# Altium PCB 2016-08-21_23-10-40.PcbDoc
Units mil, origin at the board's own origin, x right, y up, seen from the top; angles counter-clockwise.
Board outline 3246 x 2920 mil, 4 copper layers (Top Layer, MidLayer1, MidLayer2, Bottom Layer); 48 components, 32 nets, 132 pads, 110 vias.
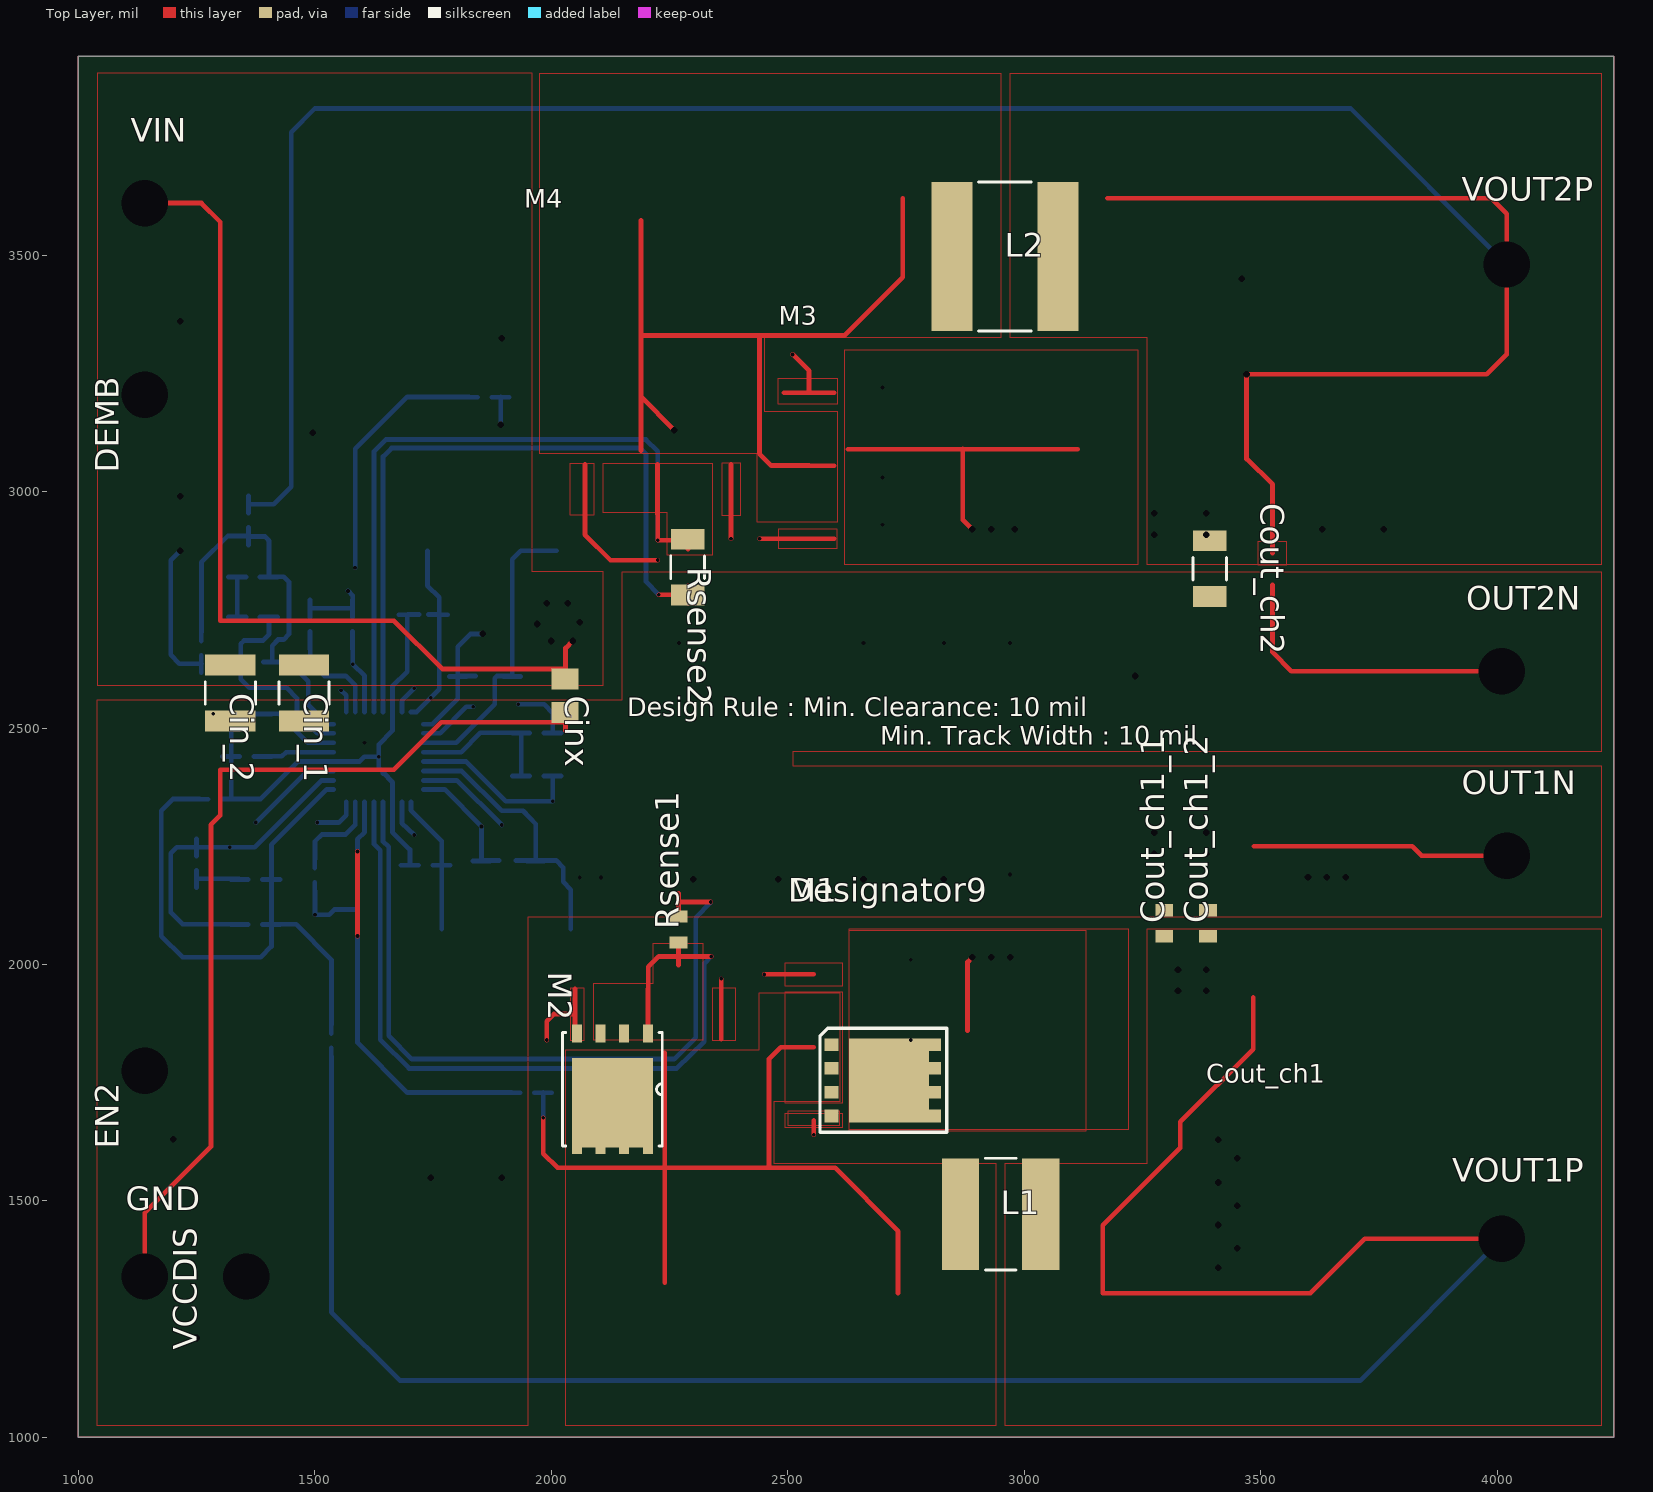
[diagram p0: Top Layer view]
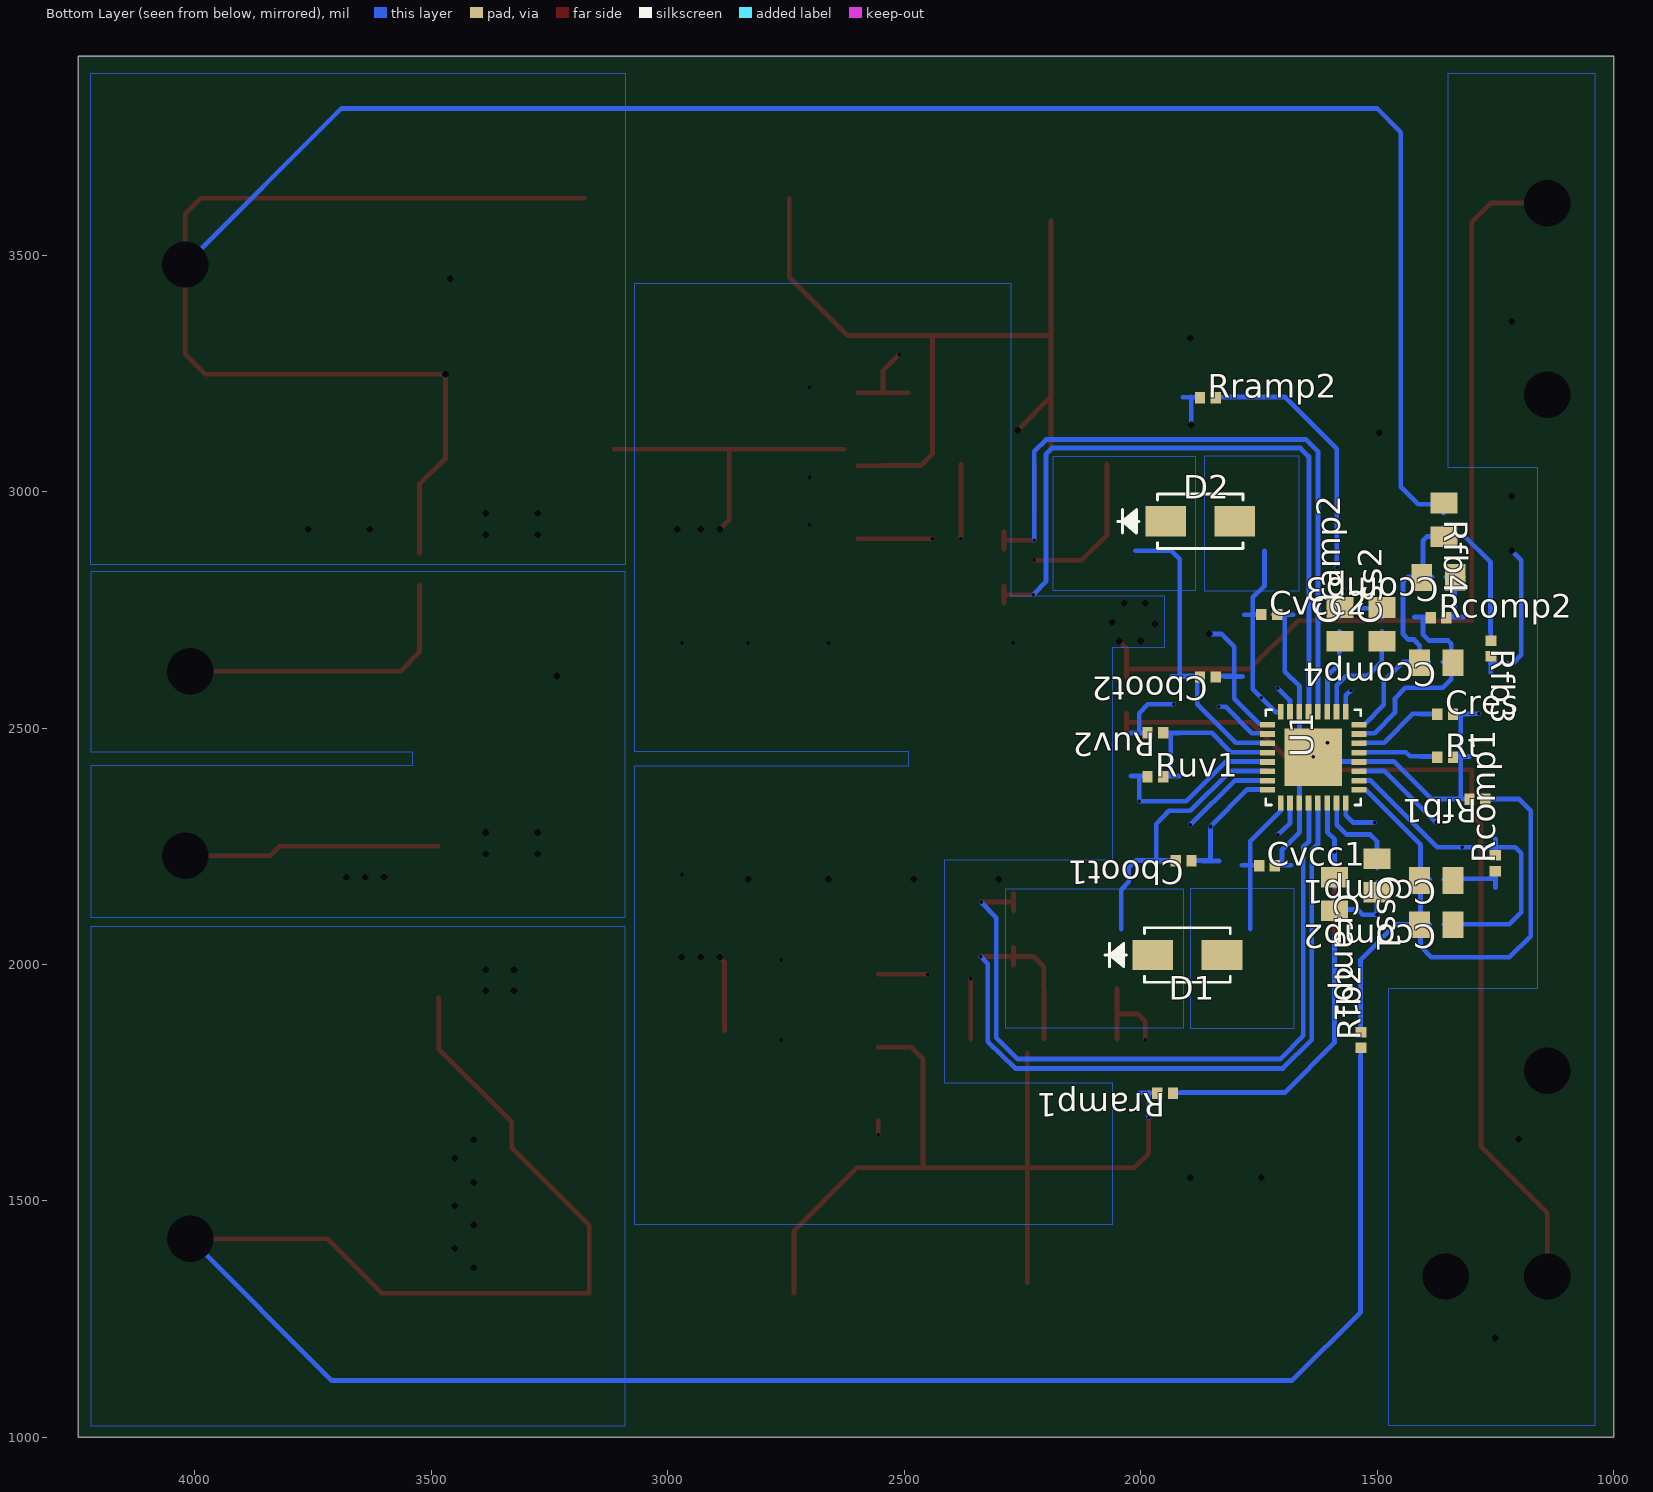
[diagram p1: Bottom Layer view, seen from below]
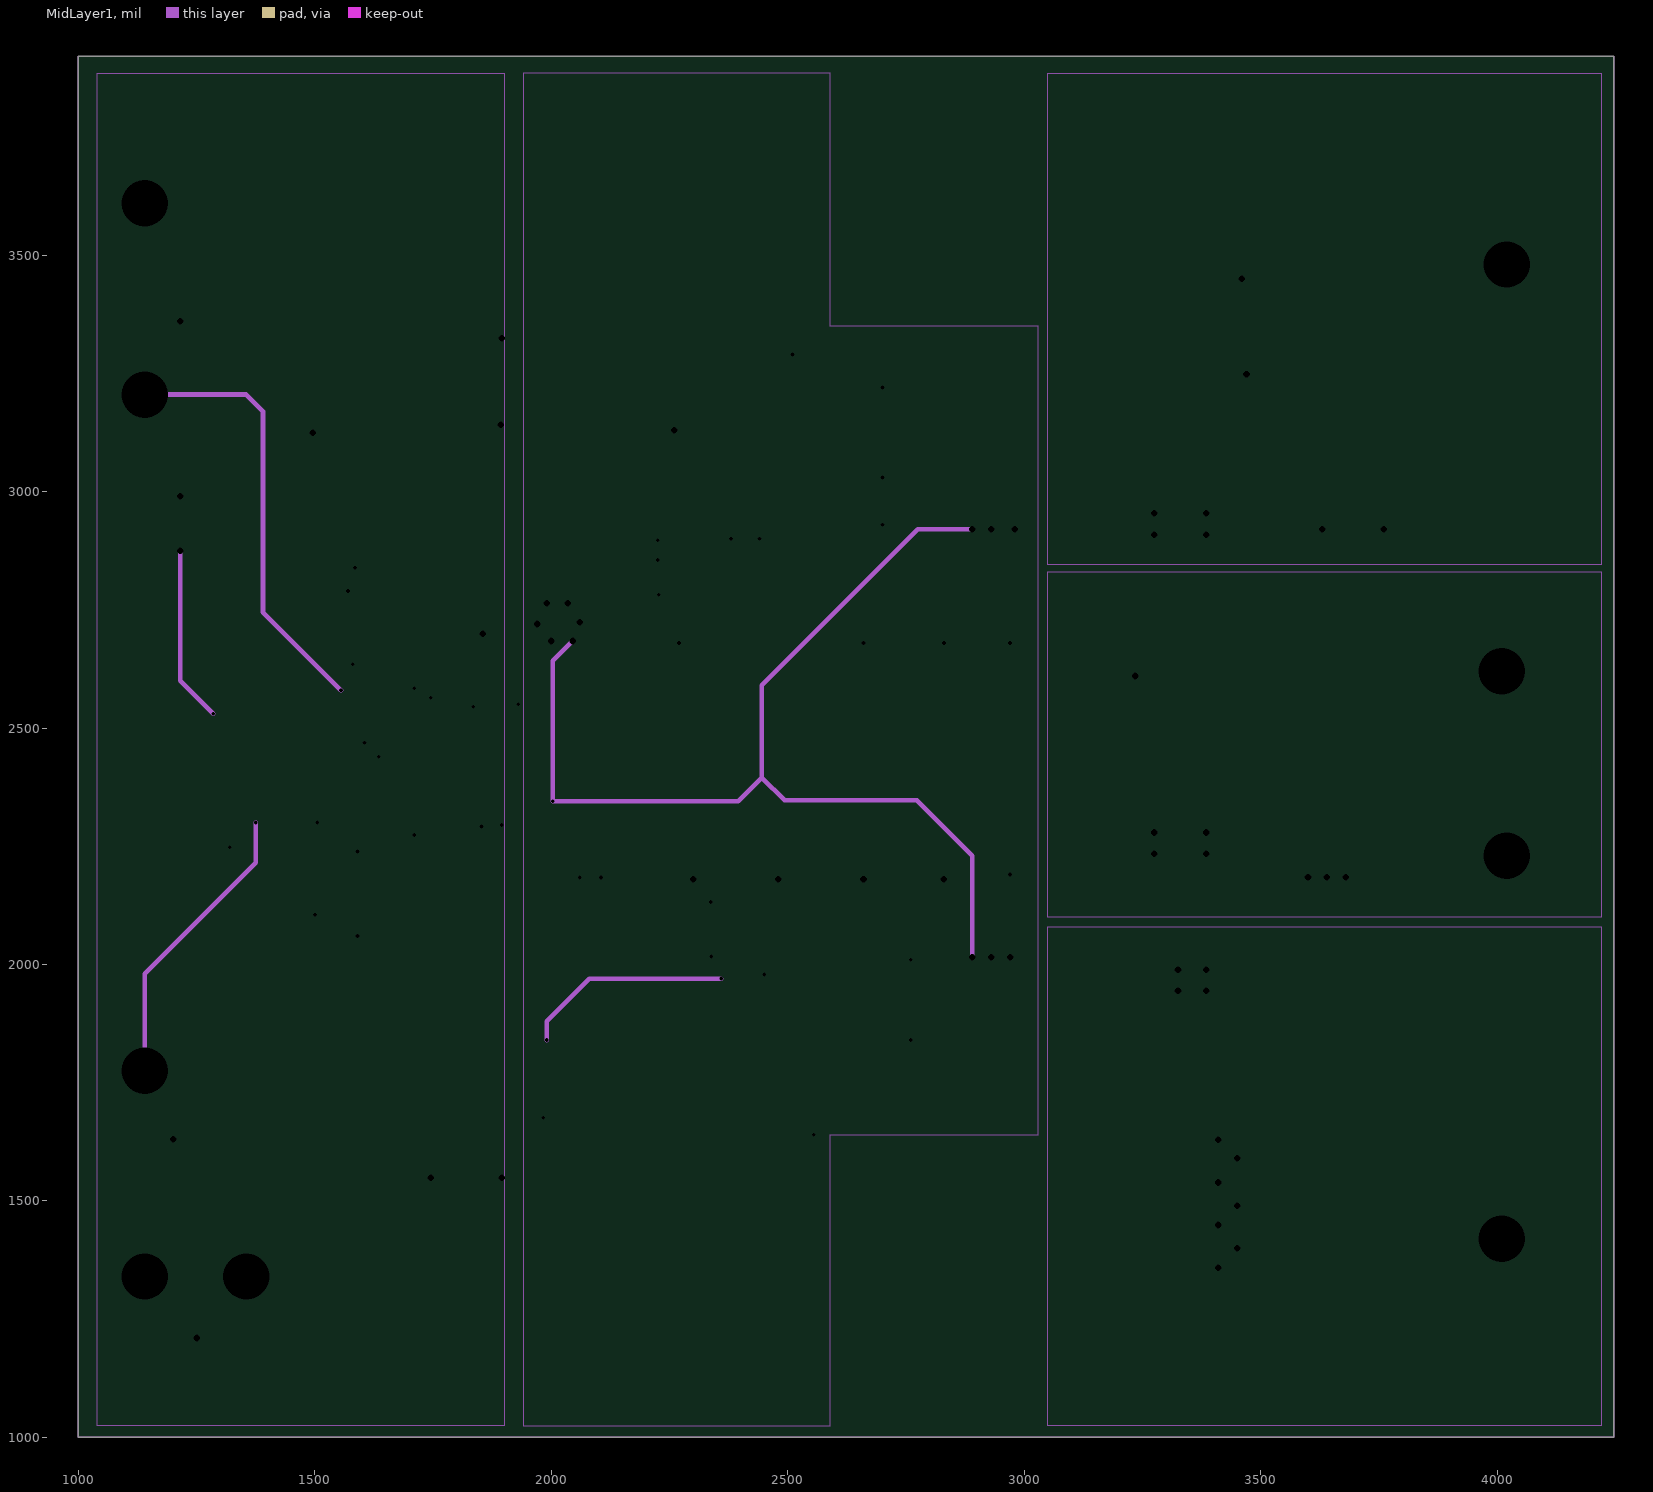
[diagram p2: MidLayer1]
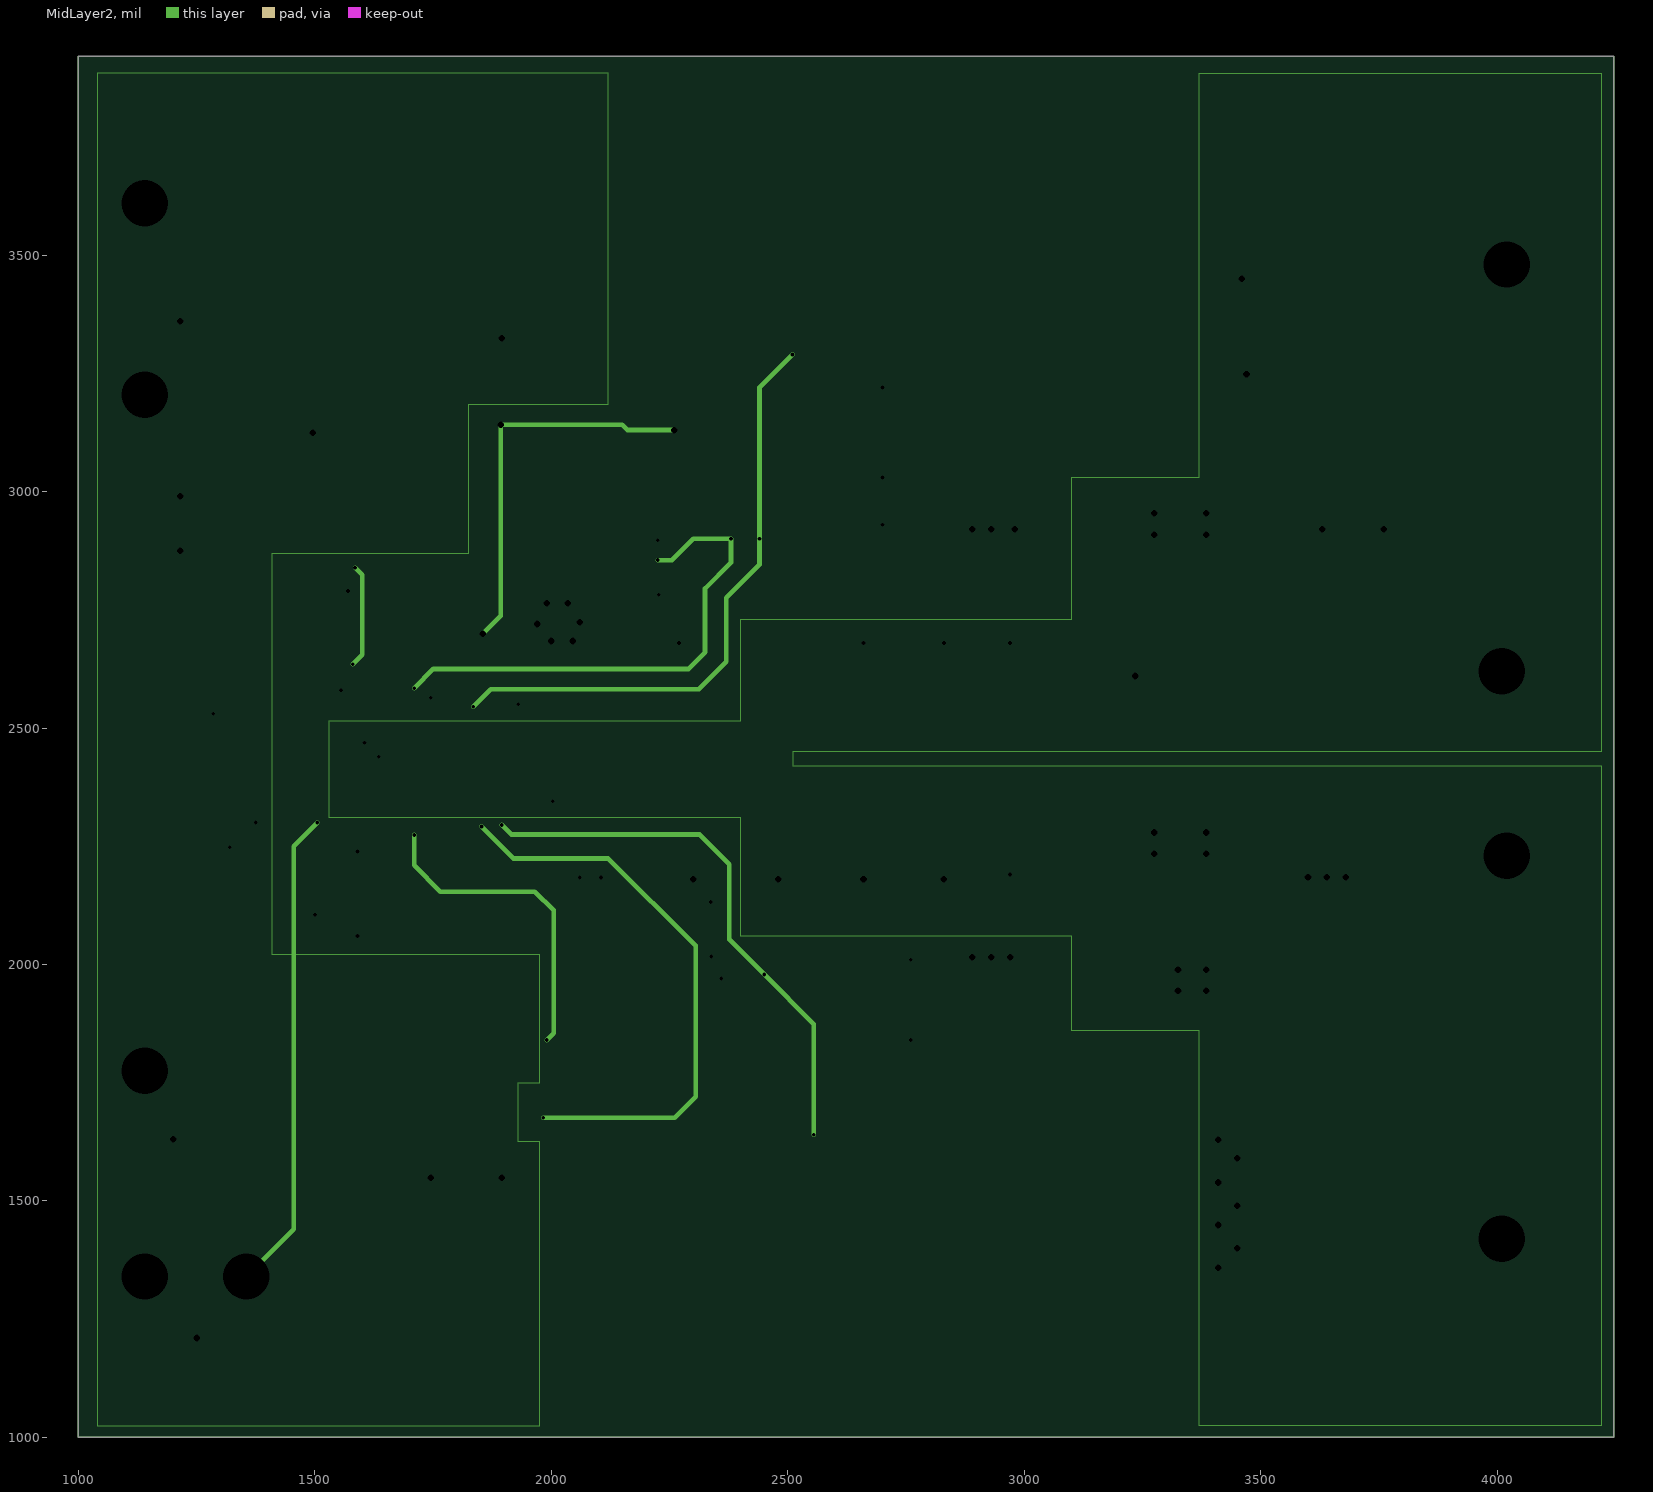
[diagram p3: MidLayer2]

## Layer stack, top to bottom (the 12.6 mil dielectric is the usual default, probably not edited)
Top Layer: signal copper 1.4
Dielectric: core 12.6, FR-4, Dk 4.8
MidLayer1: signal copper 1.4
Dielectric: prepreg 12.6, FR-4, Dk 4.8
MidLayer2: signal copper 1.4
Dielectric: core 12.6, FR-4, Dk 4.8
Bottom Layer: signal copper 1.4

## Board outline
1000,1000 4246,1000 4246,3920 1000,3920

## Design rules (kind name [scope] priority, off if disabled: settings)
PlaneConnect [All] p0: scope1count=1 scope1_0_kind=Board scope1_0_value=Board scope2count=1 scope2_0_kind=Board scope2_0_value=Board commentlength=0 planeconnectstyle=Direct reliefexpansion=20 reliefentries=4 reliefconductorwidth=10 reliefairgap=10
PlaneConnect [All] p1: planeconnectstyle=Direct reliefexpansion=20 reliefentries=4 reliefconductorwidth=10 reliefairgap=10
PolygonConnect [All] p0: scope1count=1 scope1_0_kind=Board scope1_0_value=Board scope2count=1 scope2_0_kind=Board scope2_0_value=Board commentlength=0 connectstyle=Direct reliefconductorwidth=10 reliefentries=4 polygonreliefangle="90 Angle"
PolygonConnect [All] p1: connectstyle=Direct reliefconductorwidth=10 reliefentries=4 polygonreliefangle="90 Angle"

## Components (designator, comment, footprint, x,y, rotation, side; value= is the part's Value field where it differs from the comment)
Cboot1 "" 0402 1909,2219 r180 bottom
Cboot2 "" 0402 1858,2608 r180 bottom
Ccomp1 "" 0805#1 1375,2178 r180 bottom
Ccomp2 "" 0805#1 1375,2084 r180 bottom
Ccomp3 "" 0805#1 1370,2818 r180 bottom
Ccomp4 "" 0805#1 1375,2638 r180 bottom
Cin_1 "" 1210_280 1477,2574 r270 top
Cin_2 "" 1210_280 1321,2574 r270 top
Cinx "" 0805#2 2029,2568 r270 top
Cout_ch1_1 "" 0603 3296,2087 r90 top
Cout_ch1_2 "" 0603 3388,2087 r90 top
Cout_ch2 "" 1206_190 3392,2837 r270 top
Cramp1 "" 0805#1 1590,2149 r90 bottom
Cramp2 "" 0805#1 1578,2719 r270 bottom
Cres "" 0402 1356,2529 r0 bottom
Css1 "" 0805#1 1500,2188 r90 bottom
Css2 "" 0805#1 1490,2719 r270 bottom
Cvcc1 "" 0402 1733,2209 r0 bottom
Cvcc2 "" 0402 1728,2740 r0 bottom
D1 "" SMA 1901,2020 r0 bottom
D2 "" SMA 1874,2937 r0 bottom
DEMB "" TP-1502 1138,3203 r90 top
EN2 "" TP-1502 1138,1774 r90 top
GND "" TP-1502 1138,1340 r0 top
L1 "" SRN6045 2950,1472 r0 top
L2 "" SRN8040 2959,3497 r0 top
M1 "" TRANS_NexFET_Q5A 2702,1755 r0 top
M2 "" PG-TDSON-8 2129,1736 r270 top
OUT1N "" TP-1502 4019,2228 r0 top
OUT2N "" TP-1502 4009,2620 r0 top
Rcomp1 "" 0402 1250,2214 r270 bottom
Rcomp2 "" 0402 1370,2733 r0 bottom
Rfb1 "" 0402 1288,2349 r180 bottom
Rfb2 "" 0402 1534,1840 r270 bottom
Rfb3 "" 0402 1259,2668 r90 bottom
Rfb4 "" 0805#1 1358,2940 r90 bottom
Rramp1 "" 0402 1948,1728 r180 bottom
Rramp2 "" 0402 1858,3198 r0 bottom
Rsense1 "" 0603 2269,2074 r90 top
Rsense2 "" 1206 2288,2840 r270 top
Rt "" 0402 1356,2438 r0 bottom
Ruv1 "" 0402 1969,2397 r0 bottom
Ruv2 "" 0402 1969,2490 r180 bottom
U1 "" SQA32A 1635,2438 r270 bottom
VCCDIS "" TP-1502 1353,1340 r90 top
VIN "" TP-1502 1138,3608 r0 top
VOUT1P "" TP-1502 4009,1418 r0 top
VOUT2P "" TP-1502 4019,3478 r0 top

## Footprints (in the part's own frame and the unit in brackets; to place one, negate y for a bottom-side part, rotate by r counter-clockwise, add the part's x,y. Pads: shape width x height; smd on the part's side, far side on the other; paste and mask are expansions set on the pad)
0402 [mil]
  rect 22x24 smd: 1(16.5,0) 2(-16.5,0)
0603 [mil]
  rect 26x38 smd: 1(-27.5,0) 2(27.5,0)
0805#1 [mil]
  rect 44x57 smd: 1(35.5,0) 2(-35.5,0)
0805#2 [mil]
  rect 44x57 smd: 1(-35.5,0) 2(35.5,0)
1206 [mil]
  rect 44x71 smd: 1(-59,0) 2(59,0)
  silkscreen extent -24,-36 24,36
1206_190 [mil]
  rect 44x71 smd: 1(-59,0) 2(59,0)
  silkscreen extent -24,-36 24,36
1210_280 [mil]
  rect 44x106 smd: 1(-59,0) 2(59,0)
  silkscreen extent -24,-53 24,53
PG-TDSON-8 [mil]
  rect 38x21 smd: 1(-118,75) 2(-118,25) 3(-118,-25) 4(-118,-75) 5(118,-75) 6(118,-25) 7(118,25) 8(118,75)
  rect 189.17x171.65 smd: 9(28.54,0)
  silkscreen extent -120,-106 120,106
SMA [mil]
  rect 86x64 smd: 1(73,0) 2(-73,0)
  silkscreen extent -90,-58 174,58
SQA32A [mil]
  rect 32x12 smd: 1(96.5,-68.9) 2(96.5,-49.21) 3(96.5,-29.53) 4(96.5,-9.84) 5(96.5,9.84) 6(96.5,29.53) 7(96.5,49.21) 8(96.5,68.9) 17(-96.5,68.9) 18(-96.5,49.21) 19(-96.5,29.53) 20(-96.5,9.84) 21(-96.5,-9.84) 22(-96.5,-29.53) 23(-96.5,-49.21) 24(-96.5,-68.9)
  rect 12x32 smd: 9(68.9,96.5) 10(49.21,96.5) 11(29.53,96.5) 12(9.84,96.5) 13(-9.84,96.5) 14(-29.53,96.5) 15(-49.21,96.5) 16(-68.9,96.5) 25(-68.9,-96.5) 26(-49.21,-96.5) 27(-29.53,-96.5) 28(-9.84,-96.5) 29(9.84,-96.5) 30(29.53,-96.5) 31(49.21,-96.5) 32(68.9,-96.5)
  rect 122x122 smd: 33(0,0)
  silkscreen extent -101,-101 101,101
SRN6045 [mm]
  rect 2x6 smd: 1(-2.15,0) 2(2.15,0)
  silkscreen extent -0.82,-3 0.82,3
SRN8040 [mm]
  rect 2.2x8 smd: 1(-2.85,0) 2(2.85,0)
  silkscreen extent -1.42,-4 1.42,4
TP-1502 [mil]
  round 65 / inner round 0 / far side round 65 hole 32: 1(0,0)
TRANS_NexFET_Q5A [mm]
  rect 0.75x0.675 smd: 1(-2.776,1.917) 2(-2.776,0.639) 3(-2.776,-0.639) 4(-2.776,-1.917)
  rect 0.655x0.675 smd: 5(2.776,-1.917) 6(2.776,-0.639) 7(2.776,0.639) 8(2.776,1.917)
  rect 4.295x4.51 smd: 9(0.301,0)
  silkscreen extent -3.4,-2.8 3.4,2.8

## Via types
v1: diameter 0, hole 14, Top Layer to Bottom Layer, 55 vias
v2: diameter 0, hole 8, Top Layer to Bottom Layer, 46 vias
v3: diameter 0, hole 98, Top Layer to Bottom Layer, 9 vias

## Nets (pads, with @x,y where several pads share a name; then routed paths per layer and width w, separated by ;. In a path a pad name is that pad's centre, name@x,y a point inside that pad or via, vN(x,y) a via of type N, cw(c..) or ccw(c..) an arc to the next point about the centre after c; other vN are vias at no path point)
0: Cin_1.2 Cin_2.2 Cinx.2 Cout_ch1_1.2 Cout_ch1_2.2 Cout_ch2.2 Cramp1.2 Cramp2.2 Cres.2 Css1.2 Css2.2 Cvcc1.2 Cvcc2.2 GND.1 OUT1N.1 OUT2N.1 Rfb1.2 Rfb3.2 Rsense1.2 Rsense2.2 Rt.2 Ruv2.2 U1.3 U1.4 U1.12 U1.21 U1.22 U1.33 | length 8919.6
  Top Layer w10: v3(1140,1340) 1140,1475 1280,1615 1280,2295 1300,2315 1300,2412 1667,2412 1767,2512 Cinx.2@2030,2512 ; 2030,2494 Cinx.2@2030,2531 ; v2(2227,2782) Rsense2.2@2290,2782 ; Rsense1.2@2269,2113 2269,2150 ; 2270,2132 v2(2337,2132) ; Rsense2.2@2289,2764 Rsense2.2@2289,2801 ; 3486,2250 3820,2250 3840,2230 v3(4020,2230) ; 3525,2803 3525,2660 3565,2620 v3(4010,2620)
  MidLayer1 w10: v1(1215,2875) 1215,2600 v2(1285,2530)
  Bottom Layer w10: v1(1215,2875) 1195,2855 1195,2655 1213,2636 1260,2636 ; 1259.5,2617 Rfb3.2@1259.5,2654 ; v2(1285,2530) 1323,2530 1323,2440 1323,2439 1323,2350 ; Rfb1.2@1300,2350 1323,2350 ; Rfb1.2@1304,2349.5 1341,2349.5 ; 1304,2439.5 Rt.2@1341,2439.5 ; 1304,2529.5 Cres.2@1341,2529.5 ; Css2.2@1489.5,2734 Css2.2@1489.5,2771 ; Css2.2@1490,2753 1580,2753 1580,2780 v2(1570,2790) ; Css1.2@1499.5,2137 Css1.2@1499.5,2174 ; Css1.2@1500,2156 v2(1500,2105) 1530,2105 1541,2116 Cramp1.2@1590,2116 ; Cramp2.2@1579.5,2734 Cramp2.2@1579.5,2771 ; Cramp1.2@1589.5,2097 Cramp1.2@1589.5,2134 ; U1.4@1644,2344 1644,2260 1656,2249 1656,1849 1705,1800 2260,1800 2305,1845 2305,2099 v2(2337,2132) ; U1.33@1644,2404 U1.33@1645,2405 ; U1.21@1644,2534 1644,3074 1662,3092 2188,3092 2200,3080 2200,2810 v2(2227,2782) ; 1677,2739.5 Cvcc2.2@1714,2739.5 ; 1682,2209.5 Cvcc1.2@1719,2209.5 ; 1695,2738 1695,2619 1664,2588 1664,2534 1664,2494 1635,2465 v2(1635,2439) ; 1696,2740 Cvcc2.2@1720,2740 ; 1701,2210 1701,2243 1664,2280 1664,2344 1664,2385 U1.33@1645,2405 ; v2(1930,2550) 1985,2550 2003,2531 2003,2490 ; Ruv2.2@1984,2489.5 2021,2489.5 ; 1323,2350 1385,2350 1464,2429 1540,2429 1594,2429 1604,2439 v2(1635,2439) ; v2(1635,2439) 1635,2415 U1.33@1645,2405
  other v1: 1250,1210 1745,1549 1895,1549 1200,1630 2300,2180 2480,2180 2660,2180 2830,2180 3600,2184 3640,2184 3680,2184 3275,2234 3385,2234 3275,2279 3385,2279 3235,2610 1215,2990 1495,3124 1895,3324 1215,3360
  other v2: 2060,2184 2105,2184 2970,2190 1605,2469 2270,2680 2660,2680 2830,2680 2970,2680
1: Cin_1.1 Cin_2.1 Cinx.1 M1.5 M1.6 M1.7 M1.8 M1.9 Ruv1.1 U1.29 VIN.1 | length 5441.4
  Top Layer w10: v3(1140,3610) 1260,3610 1300,3570 1300,2727 1667,2727 1769,2625 2030,2625 2030,2669 v1(2045,2684) ; Cinx.1@2030,2608 2030,2645 ; 2627,3089.5 3113,3089.5 ; 2870,3090 2870,2940 v1(2890,2920) ; 2880,1860 2880,2005 v1(2890,2015)
  MidLayer1 w10: v1(2045,2684) 2003,2642 v2(2003,2345) 2395,2345 2445,2395 ; v1(2890,2015) 2890,2230 2773,2347 2493,2347 2445,2395 ; v1(2890,2920) 2775,2920 2445,2590 2445,2395
  Bottom Layer w10: U1.29@1729,2429 1820,2429 1904,2345 v2(2003,2345) 2003,2399 ; Ruv1.1@1984,2398.5 2021,2398.5
  other v1: 2930,2015 2970,2015 2000,2684 1970,2720 2060,2724 1990,2764 2035,2764 2930,2920 2980,2920
  other v2: 2760,1840 2760,2010 2700,2930 2700,3030 2700,3220
2: Ruv1.2 Ruv2.1 U1.28 | length 389
  Bottom Layer w10: U1.28@1729,2449 1809,2449 1850,2490 1936,2490 1936,2399 ; 1917,2398.5 Ruv1.2@1954,2398.5 ; 1917,2489.5 Ruv2.1@1954,2489.5
3: Cout_ch1_1.1 Cout_ch1_2.1 L1.2 Rfb2.1 VOUT1P.1 | length 4885.7
  Top Layer w10: 3484,1930 3484,1821 3330,1667 3330,1612 3166,1448 3166,1305 3605,1305 3720,1420 v3(4010,1420)
  Bottom Layer w10: 1534.5,1787 Rfb2.1@1534.5,1824 ; 1535,1806 1535,1265 1680,1120 3710,1120 v3(4010,1420)
  other v1: 3410,1359 3450,1400 3410,1449 3450,1490 3410,1539 3450,1590 3410,1629 3325,1944 3385,1944 3325,1989 3385,1989
4: Ccomp2.1 Rcomp1.2 U1.10 | length 764.1
  Bottom Layer w10: Rcomp1.2@1249.5,2229 1249.5,2266 ; Ccomp2.1@1322,2084.5 Ccomp2.1@1359,2084.5 ; Ccomp2.1@1341,2085 1220,2085 1195,2110 1195,2235 1208,2248 1250,2248 v2(1320,2248) 1373,2248 1514,2389 U1.10@1540,2389
5: Ccomp1.2 Ccomp2.2 Rfb1.1 Rfb2.2 U1.9 | length 1456.1
  Bottom Layer w10: 1237,2349.5 Rfb1.1@1274,2349.5 ; 1256,2350 1200,2350 1175,2325 1175,2060 1220,2015 1385,2015 1408,2038 Ccomp2.2@1408,2085 ; Ccomp2.2@1389,2084.5 Ccomp2.2@1426,2084.5 ; Ccomp1.2@1389,2179.5 Ccomp1.2@1426,2179.5 ; Rfb2.2@1534.5,1854 1534.5,1891 ; 1535,1873 1535,2010 1460,2085 Ccomp2.2@1408,2085 ; U1.9@1540,2370 1525,2370 1408,2253 1408,2180 Ccomp2.2@1408,2085
6: Cramp2.1 Rramp2.2 U1.19 | length 992.4
  MidLayer2 w10: v2(1580,2635) 1600,2655 1600,2824 v2(1585,2839)
  Bottom Layer w10: Cramp2.1@1579.5,2667 Cramp2.1@1579.5,2704 ; Cramp2.1@1580,2686 v2(1580,2635) 1605,2610 U1.19@1605,2534 ; v2(1585,2839) 1585,3090 1695,3200 1826,3200 ; 1807,3199.5 Rramp2.2@1844,3199.5
7: Cramp1.1 Rramp1.1 U1.6 | length 1015.4
  Top Layer w10: v2(1590,2060) v2(1590,2239)
  Bottom Layer w10: Cramp1.1@1589.5,2164 Cramp1.1@1589.5,2201 ; v2(1590,2060) 1590,1835 1695,1729 1916,1729 ; Cramp1.1@1590,2183 v2(1590,2239) 1590,2265 1605,2280 U1.6@1605,2344 ; 1897,1728.5 Rramp1.1@1934,1728.5
8: Ccomp1.1 Rcomp1.1 | length 165.4
  Bottom Layer w10: 1249.5,2162 Rcomp1.1@1249.5,2199 ; 1250,2181 1340,2181 Ccomp1.1@1341,2180 ; Ccomp1.1@1322,2179.5 Ccomp1.1@1359,2179.5
9: Ccomp4.1 Rcomp2.1 U1.15 | length 516.4
  Bottom Layer w10: Ccomp4.1@1324,2639.5 Ccomp4.1@1361,2639.5 ; Rcomp2.1@1384,2734.5 1421,2734.5 ; 1403,2735 1403,2698 1390,2685 1350,2685 1343,2678 1343,2640 1343,2603 1361,2585 1440,2585 1462,2563 1462,2533 1505,2489 U1.15@1540,2489
10: Cres.1 U1.14 | length 212.6
  Bottom Layer w10: Cres.1@1371,2529.5 1408,2529.5 ; 1390,2530 1425,2530 1485,2469 U1.14@1540,2469
11: U1.23 | length 1733.3
  Top Layer w10: 2071,2952 2071,3058 ; 2071,3005 2071,2909 2125,2855 v2(2225,2855) ; v2(2380,2900) 2380,3005 ; 2380,2952 2380,3058
  MidLayer2 w10: v2(1710,2584) 1750,2625 2290,2625 2325,2660 2325,2795 2380,2850 v2(2380,2900) 2300,2900 2255,2855 v2(2225,2855)
  Bottom Layer w10: U1.23@1684,2534 1684,2558 v2(1710,2584)
12: U1.26 | length 1824.3
  Top Layer w10: v2(2440,2900) 2545,2900 ; 2492,2900 2598,2900 ; 2492,3209 2598,3209 ; v2(2510,3290) 2545,3255 2545,3209
  MidLayer2 w10: v2(1835,2545) 1872,2582 2312,2582 2370,2640 2370,2775 2440,2845 v2(2440,2900) 2440,3220 v2(2510,3290)
  Bottom Layer w10: U1.26@1729,2489 1765,2489 1820,2545 v2(1835,2545)
13: Rt.1 U1.13 | length 190.7
  Bottom Layer w10: Rt.1@1371,2439.5 1408,2439.5 ; 1390,2440 1430,2440 1439,2449 U1.13@1540,2449
14: M1.4 U1.31 | length 1501.2
  Top Layer w10: v2(2450,1979) 2555,1979 ; v2(2555,1640) 2555,1670
  MidLayer2 w10: v2(1895,2295) 1915,2275 2313,2275 2376,2212 2376,2053 v2(2450,1979) 2555,1874 v2(2555,1640)
  Bottom Layer w10: U1.31@1729,2389 1800,2389 v2(1895,2295)
15: Cboot1.1 L1.1 M1.1 M1.2 M1.3 M2.5 M2.6 M2.7 M2.8 M2.9 Rramp1.2 U1.32 | length 3456.2
  Top Layer w10: v2(1983,1676) 1983,1600 2013,1570 2240,1570 2460,1570 ; 2239.5,1327 2239.5,1813 ; 2555,1825 2485,1825 2460,1800 2460,1570 ; 2733,1305 2733,1436 2600,1570 2460,1570
  MidLayer2 w10: v2(1852,2292) 1920,2224 2120,2224 2305,2040 2305,1720 2261,1676 v2(1983,1676)
  Bottom Layer w10: U1.32@1729,2370 1774,2370 v2(1852,2292) 1852,2220 Cboot1.1@1890,2220 ; 1834,2219 1871,2219 ; Rramp1.2@1964,1728.5 2001,1728.5 ; v2(1983,1676) 1983,1729
16: Cvcc1.1 D1.2 U1.1 | length 332.9
  Bottom Layer w10: U1.1@1703,2344 1703,2326 1768,2261 1768,2210 1768,2209 1768,2075 ; Cvcc1.1@1749,2209.5 1786,2209.5
17: Cvcc2.1 D2.2 U1.24 | length 443.2
  Bottom Layer w10: U1.24@1703,2534 1715,2534 v2(1745,2564) 1763,2582 1763,2740 ; 1738,2875 1738,2801 1763,2776 1763,2740 ; Cvcc2.1@1740,2740 1763,2740 ; Cvcc2.1@1744,2739.5 1781,2739.5
18: Cboot2.1 L2.1 Rramp2.1 U1.25 | length 3227.1
  Top Layer w10: 2189.5,3087 2189.5,3573 ; v1(2260,3130) 2190,3200 2190,3330 2440,3330 ; 2492,3054.5 2598,3054.5 ; 2545,3055 2465,3055 2440,3080 2440,3330 ; 2743,3620 2743,3453 2620,3330 2440,3330
  MidLayer2 w10: v1(1855,2699) 1893,2737 v1(1893,3141) 2150,3141 2161,3130 v1(2260,3130)
  Bottom Layer w10: U1.25@1729,2508 1748,2508 1802,2562 1802,2610 ; 1784,2609 1821,2609 ; Cboot2.1@1840,2610 1802,2610 ; v1(1855,2699) 1829,2699 1802,2672 1802,2610 ; Rramp2.1@1874,3199.5 1911,3199.5 ; v1(1893,3141) 1893,3200
19: Cboot2.2 D2.1 U1.27 | length 664.1
  Bottom Layer w10: U1.27@1729,2469 1799,2469 1880,2550 1880,2605 1885,2610 1917,2610 1917,2857 1935,2875 2011,2875 ; 1898,2609 1935,2609
20: Cboot1.2 D1.1 U1.30 | length 641
  Bottom Layer w10: U1.30@1729,2409 1810,2409 1895,2325 1940,2325 1967,2297 1967,2220 ; Cboot1.2@1925,2220 1967,2220 ; 1948,2219 1985,2219 ; 2041,2075 2041,2158 2025,2175 2025,2205 2010,2220 1967,2220
21: Rsense2.1 U1.20 | length 1675.7
  Top Layer w10: 2224.5,2952 2224.5,3058 ; 2225,3005 v2(2225,2897) Rsense2.1@2290,2897 ; Rsense2.1@2289,2878 Rsense2.1@2289,2915
  Bottom Layer w10: U1.20@1625,2534 1625,3085 1650,3110 2200,3110 2225,3085 v2(2225,2897)
22: M2.4 U1.2 | length 1600.1
  Top Layer w10: v2(1990,1840) 1990,1880 2005,1895 2050,1895 ; M2.4@2050,1842 2050,1948 ; 2359,1842 2359,1948 ; 2359,1895 v2(2359,1970)
  MidLayer1 w10: v2(1990,1840) 1990,1880 2080,1970 v2(2359,1970)
  MidLayer2 w10: v2(1710,2274) 1710,2210 1765,2154 1965,2154 2005,2115 2005,1855 v2(1990,1840)
  Bottom Layer w10: U1.2@1684,2344 1684,2299 v2(1710,2274)
23: Cout_ch2.1 L2.2 Rfb4.1 VOUT2P.1 | length 5742.9
  Top Layer w10: 3176,3620 3987,3620 4020,3587 v3(4020,3480) 4020,3290 3978,3248 v1(3470,3248) 3470,3069 3525,3015 3525,2870
  Bottom Layer w10: Rfb4.1@1359.5,2954 Rfb4.1@1359.5,2991 ; Rfb4.1@1360,2973 1413,2973 1450,3010 1450,3760 1500,3810 3690,3810 v3(4020,3480)
  other v1: 3275,2909 3385,2909 3630,2920 3760,2920 3275,2954 3385,2954 3460,3450
24: Ccomp3.2 Ccomp4.2 Rfb3.1 Rfb4.2 U1.16 | length 991.3
  Bottom Layer w10: Rfb3.1@1259.5,2684 1259.5,2721 ; 1260,2703 1260,2850 1316,2906 Rfb4.2@1360,2906 ; Rfb4.2@1359.5,2887 Rfb4.2@1359.5,2924 ; Rfb4.2@1361,2905 1395,2905 1403,2896 1403,2820 1434,2820 1445,2809 1445,2698 1434,2687 1422,2687 1410,2674 1410,2640 1445,2640 1486,2599 1486,2549 1526,2508 U1.16@1540,2508 ; Ccomp3.2@1384,2819.5 Ccomp3.2@1421,2819.5 ; Ccomp4.2@1391,2639.5 Ccomp4.2@1428,2639.5
25: M2.1 M2.2 M2.3 Rsense1.1 U1.5 | length 1813.3
  Top Layer w10: M2.1@2204.5,1842 2204.5,1948 ; 2205,1895 2205,1995 2227,2017 2270,2017 v2(2338,2017) ; 2269,1999 Rsense1.1@2269,2036
  Bottom Layer w10: U1.5@1625,2344 1625,2254 1638,2241 1638,1841 1699,1780 2265,1780 2323,1837 2323,2002 v2(2338,2017)
26: Ccomp3.1 Rcomp2.2 | length 159
  Bottom Layer w10: 1317,2734.5 Rcomp2.2@1354,2734.5 ; Ccomp3.1@1317,2819.5 Ccomp3.1@1354,2819.5 ; 1336,2735 Ccomp3.1@1336,2820
27: Css1.1 U1.7 | length 222.5
  Bottom Layer w10: Css1.1@1499.5,2204 Css1.1@1499.5,2241 ; Css1.1@1500,2223 1500,2260 1515,2275 1565,2275 1585,2295 U1.7@1585,2344
28: Css2.1 U1.18 | length 254.7
  Bottom Layer w10: Css2.1@1489.5,2667 Css2.1@1489.5,2704 ; Css2.1@1490,2686 1490,2640 1520,2610 1565,2610 1585,2590 U1.18@1585,2534
36: U1.8 VCCDIS.1 | length 1117.8
  MidLayer2 w10: v3(1355,1340) 1455,1440 1455,2250 v2(1505,2300)
  Bottom Layer w10: v2(1505,2300) 1550,2300 1566,2316 U1.8@1566,2344
50: EN2.1 U1.11 | length 832.5
  MidLayer1 w10: v3(1140,1775) 1140,1980 1375,2215 v2(1375,2300)
  Bottom Layer w10: v2(1375,2300) 1484,2409 U1.11@1540,2409
57: DEMB.1 U1.17 | length 973.4
  MidLayer1 w10: v3(1140,3205) 1355,3205 1390,3170 1390,2745 v2(1555,2580)
  Bottom Layer w10: v2(1555,2580) 1566,2569 U1.17@1566,2534

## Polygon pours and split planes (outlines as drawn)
1 on Bottom Layer " " (solid, pour order 24): 1950,2780 1950,2670 2060,2670 2060,2220 2415,2220 2415,1750 2060,1750 2060,1450 3070,1450 3070,2420 2490,2420 2490,2450 3070,2450 3070,3440 2275,3440 2275,2780
16 on Bottom Layer " " (solid, pour order 25): 1895,2160 1895,1865 1675,1865 1675,2160
20 on Bottom Layer " " (solid, pour order 26): 1910,2160 1910,1865 2285,1865 2285,2160
17 on Bottom Layer " " (solid, pour order 27): 1865,2790 1665,2790 1665,3075 1865,3075
19 on Bottom Layer " " (solid, pour order 28): 1885,2790 2185,2790 2185,3075 1885,3075
3 on Bottom Layer " " (solid, pour order 29): 4220,1025 3090,1025 3090,2080 4220,2080
23 on Bottom Layer " " (solid, pour order 30): 3090,2845 4220,2845 4220,3885 3090,3885
0 on Bottom Layer " " (solid, pour order 36): 1040,1025 1475,1025 1475,1950 1160,1950 1160,3050 1350,3050 1350,3885 1040,3885
0 on Bottom Layer " " (solid, pour order 37): 3090,2830 4220,2830 4220,2450 3540,2450 3540,2420 4220,2420 4220,2100 3090,2100
1 on Top Layer " " (solid, pour order 0): 2630,1647 2630,2072 3130,2072 3130,1647
14 on Top Layer " " (solid, pour order 1): 2495,1655 2495,1685 2615,1685 2615,1655
15 on Top Layer " " (solid, pour order 2): 2495,1707 2495,1942 2615,1942 2615,1707
14 on Top Layer " " (solid, pour order 3): 2495,1954 2495,2004 2615,2004 2615,1954
23 on Top Layer " " (solid, pour order 4): 3495,2844 3495,2895 3554,2895 3554,2844
15 on Top Layer " " (solid, pour order 5): 2030,1025 2030,1820 2440,1820 2440,1940 2610,1940 2610,1710 2470,1710 2470,1580 2940,1580 2940,1025
11 on Top Layer " " (solid, pour order 6): 2040,3060 2090,3060 2090,2950 2040,2950
11 on Top Layer " " (solid, pour order 7): 2360,3060 2360,2950 2400,2950 2400,3060
1 on Top Layer " " (solid, pour order 8): 2630,2075 3220,2075 3220,1650 2630,1650
12 on Top Layer " " (solid, pour order 9): 2480,2920 2480,2880 2605,2880 2605,2920
12 on Top Layer " " (solid, pour order 10): 2480,3240 2605,3240 2605,3185 2480,3185
22 on Top Layer " " (solid, pour order 11): 2040,1950 2040,1840 2070,1840 2070,1950
14 on Top Layer " " (solid, pour order 12): 2500,1690 2500,1660 2610,1660 2610,1690
22 on Top Layer " " (solid, pour order 13): 2340,1950 2340,1840 2390,1840 2390,1950
25 on Top Layer " " (solid, pour order 14): 2090,1840 2090,1960 2215,1960 2215,2045 2320,2045 2320,1840
21 on Top Layer " " (solid, pour order 15): 2110,2955 2110,3060 2340,3060 2340,2865 2245,2865 2245,2955
1 on Top Layer " " (solid, pour order 16): 1040,2590 2110,2590 2110,2830 1960,2830 1960,3885 1040,3885
1 on Top Layer " " (solid, pour order 17): 2620,3300 3240,3300 3240,2845 2620,2845
18 on Top Layer " " (solid, pour order 18): 1975,3885 2950,3885 2950,3325 2450,3325 2450,3170 2605,3170 2605,2935 2435,2935 2435,3080 1975,3080
23 on Top Layer " " (solid, pour order 19): 3260,2845 3260,3325 2970,3325 2970,3885 4220,3885 4220,2845
3 on Top Layer " " (solid, pour order 20): 2960,1580 3260,1580 3260,2075 4220,2075 4220,1025 2960,1025
0 on Top Layer " " (solid, pour order 31): 1040,1025 1040,2560 2150,2560 2150,2830 4220,2830 4220,2450 2510,2450 2510,2420 4220,2420 4220,2100 1950,2100 1950,1025
1 on MidLayer1 " " (solid, pour order 21): 1940,3885 1940,1025 2590,1025 2590,1640 3030,1640 3030,3350 2590,3350 2590,3885
3 on MidLayer1 " " (solid, pour order 22): 4220,2080 4220,1025 3050,1025 3050,2080
23 on MidLayer1 " " (solid, pour order 23): 4220,2845 3050,2845 3050,3885 4220,3885
0 on MidLayer1 " " (solid, pour order 32): 1040,3885 1900,3885 1900,1025 1040,1025
0 on MidLayer1 " " (solid, pour order 33): 4220,2830 4220,2100 3050,2100 3050,2830
0 on MidLayer2 " " (solid, pour order 34): 1040,1025 1975,1025 1975,1625 1930,1625 1930,1750 1975,1750 1975,2020 1410,2020 1410,2870 1825,2870 1825,3185 2120,3185 2120,3885 1040,3885
0 on MidLayer2 " " (solid, pour order 35): 1530,2310 1530,2515 2400,2515 2400,2730 3100,2730 3100,3030 3370,3030 3370,3885 4220,3885 4220,2450 2510,2450 2510,2420 4220,2420 4220,1025 3370,1025 3370,1860 3100,1860 3100,2060 2400,2060 2400,2310

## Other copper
Multi-Layer:
  the board outline again, w1

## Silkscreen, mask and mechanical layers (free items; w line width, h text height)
Top Overlay:
  text "M4" at 1943,3600 h39
  text "M3" at 2481,3353 h39
  text "Design Rule : Min. Clearance: 10 mil" at 2160,2525 h39
  text "Min. Track Width : 10 mil" at 2695,2465 h39
  text "Cout_ch1" at 3385,1750 h39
